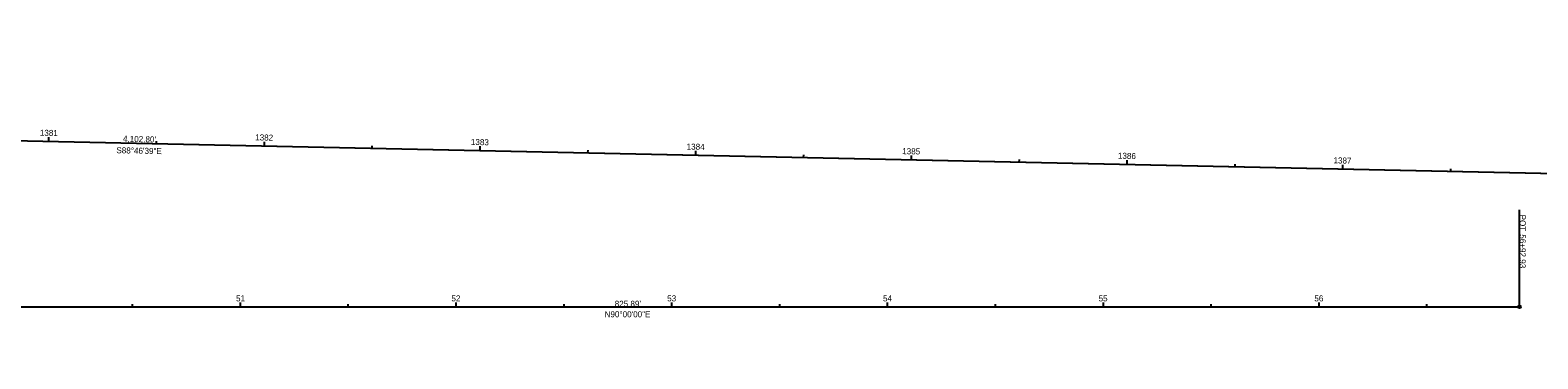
# Model space of a CAD drawing. Extents: x 1853419 to 1876817, y 661863 to 674119.
# Drawn here: x 1871324 to 1872023, y 670146 to 670299 of the extents above; entities that cross this region are included whole.
import ezdxf

# ---------------------------------------------------------------- set-up
doc = ezdxf.new("R2010")
doc.units = 0
for name, color, linetype in [('DR_X_Cells', 7, 'Continuous'), ('GE_X_Cells', 7, 'Continuous'), ('RS_Raster1', 7, 'Continuous'), ('SV_P_Control_Cells_Set', 7, 'Continuous'), ('SV_X_Control_Cells_Found', 7, 'Continuous'), ('SV_X_Random_Point', 7, 'Continuous')]:
    doc.layers.add(name, color=color, linetype=linetype)

msp = doc.modelspace()

# ---------------------------------------------------------------- linework, layer by layer
at = {"layer": 'GE_X_Cells'}
msp.add_line((1872014.54, 670170.22), (1872014.54, 670215.22), dxfattribs=at)
msp.add_circle((1872014.54, 670170.22), 0.6, dxfattribs=at)
at = {"layer": 'RS_Raster1'}
msp.add_line((1868915.68, 670298.52), (1876056.39, 670146.14), dxfattribs=at)
at = {"layer": 'SV_P_Control_Cells_Set'}
for p, q in [((1869324.34, 670289.8), (1873426.2, 670202.27)), ((1871188.66, 670170.22), (1872014.54, 670170.22))]:
    msp.add_line(p, q, dxfattribs=at)
at = {"layer": 'SV_X_Random_Point'}
for p, q in [((1871332.77, 670246.94), (1871332.81, 670248.94)), ((1871382.75, 670245.87), (1871382.78, 670247.07)), ((1871432.74, 670244.81), (1871432.79, 670246.81)), ((1871482.73, 670243.74), (1871482.76, 670244.94)), ((1871532.72, 670242.67), (1871532.76, 670244.67)), ((1871582.71, 670241.61), (1871582.73, 670242.81)), ((1871632.7, 670240.54), (1871632.74, 670242.54)), ((1871682.69, 670239.47), (1871682.71, 670240.67)), ((1871732.67, 670238.41), (1871732.72, 670240.41)), ((1871782.66, 670237.34), (1871782.69, 670238.54)), ((1871832.65, 670236.27), (1871832.69, 670238.27)), ((1871882.64, 670235.21), (1871882.67, 670236.41)), ((1871932.63, 670234.14), (1871932.67, 670236.14)), ((1871982.62, 670233.07), (1871982.64, 670234.27)), ((1871371.61, 670170.22), (1871371.61, 670171.42)), ((1871421.61, 670170.22), (1871421.61, 670172.22)), ((1871471.61, 670170.22), (1871471.61, 670171.42)), ((1871521.61, 670170.22), (1871521.61, 670172.22)), ((1871571.61, 670170.22), (1871571.61, 670171.42)), ((1871621.61, 670170.22), (1871621.61, 670172.22)), ((1871671.61, 670170.22), (1871671.61, 670171.42)), ((1871721.61, 670170.22), (1871721.61, 670172.22)), ((1871771.61, 670170.22), (1871771.61, 670171.42)), ((1871821.61, 670170.22), (1871821.61, 670172.22)), ((1871871.61, 670170.22), (1871871.61, 670171.42)), ((1871921.61, 670170.22), (1871921.61, 670172.22)), ((1871971.61, 670170.22), (1871971.61, 670171.42))]:
    msp.add_line(p, q, dxfattribs=at)

# ---------------------------------------------------------------- texts
at = {"layer": 'DR_X_Cells'}
msp.add_text("4,102.80'", height=2.8, rotation=358.77757, dxfattribs=at).set_placement((1871367.17, 670246.77))
msp.add_text("825.89'", height=2.8, dxfattribs=at).set_placement((1871595.11, 670170.27))
at = {"layer": 'GE_X_Cells'}
for s, p in [('POT', (1872014.59, 670213)), ('56+92.93', (1872014.59, 670203.87))]:
    msp.add_text(s, height=2.8, rotation=270, dxfattribs=at).set_placement(p)
at = {"layer": 'SV_X_Control_Cells_Found'}
msp.add_text('S88°46\'39"E', height=2.8, rotation=358.77757, dxfattribs=at).set_placement((1871364.1, 670241.47))
msp.add_text('N90°00\'00"E', height=2.8, dxfattribs=at).set_placement((1871590.42, 670165.42))
at = {"layer": 'SV_X_Random_Point'}
for s, p in [('1381', (1871328.62, 670249.58)), ('1382', (1871428.44, 670247.45)), ('1383', (1871528.42, 670245.31)), ('1384', (1871628.43, 670243.18)), ('1385', (1871728.35, 670241.05)), ('1386', (1871828.34, 670238.91)), ('1387', (1871928.26, 670236.78))]:
    msp.add_text(s, height=2.8, rotation=358.77757, dxfattribs=at).set_placement(p)
for s, p in [('51', (1871419.59, 670172.77)), ('52', (1871519.43, 670172.77)), ('53', (1871619.44, 670172.77)), ('54', (1871719.46, 670172.77)), ('55', (1871819.41, 670172.77)), ('56', (1871919.41, 670172.77))]:
    msp.add_text(s, height=2.8, dxfattribs=at).set_placement(p)

doc.saveas('drawing.dxf')
